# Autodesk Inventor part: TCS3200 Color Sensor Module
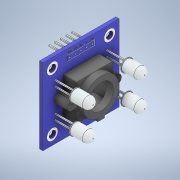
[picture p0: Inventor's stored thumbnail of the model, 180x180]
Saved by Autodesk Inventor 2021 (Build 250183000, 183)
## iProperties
Created: 2025-02
Part Number: TCS3200 Color Sensor Module
Material: Generic
Description: STEP AP214
Document SubType Name: Modeling
Designer: alolo
Density: 1 g/cm^3
Appearance: Default
Title: TCS3200 Color Sensor Module.STEP
Revision Number: ANY
Sending System: SolidWorks 2022
Preprocessor: SwSTEP 2.0
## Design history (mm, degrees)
node "Annotations"
  node "Linear Dimension 1" dims "d2" = 34 (derived)
  node "Linear Dimension 2" dims "d5" = 23 (derived)
feature "LPattern1"
body "Solid1"
other parameters: "d0" = 5.69991 (derived), "d1" = 4.81473 (derived), "d3" = 5.89046 (derived), "d4" = 5.53428 (derived)
